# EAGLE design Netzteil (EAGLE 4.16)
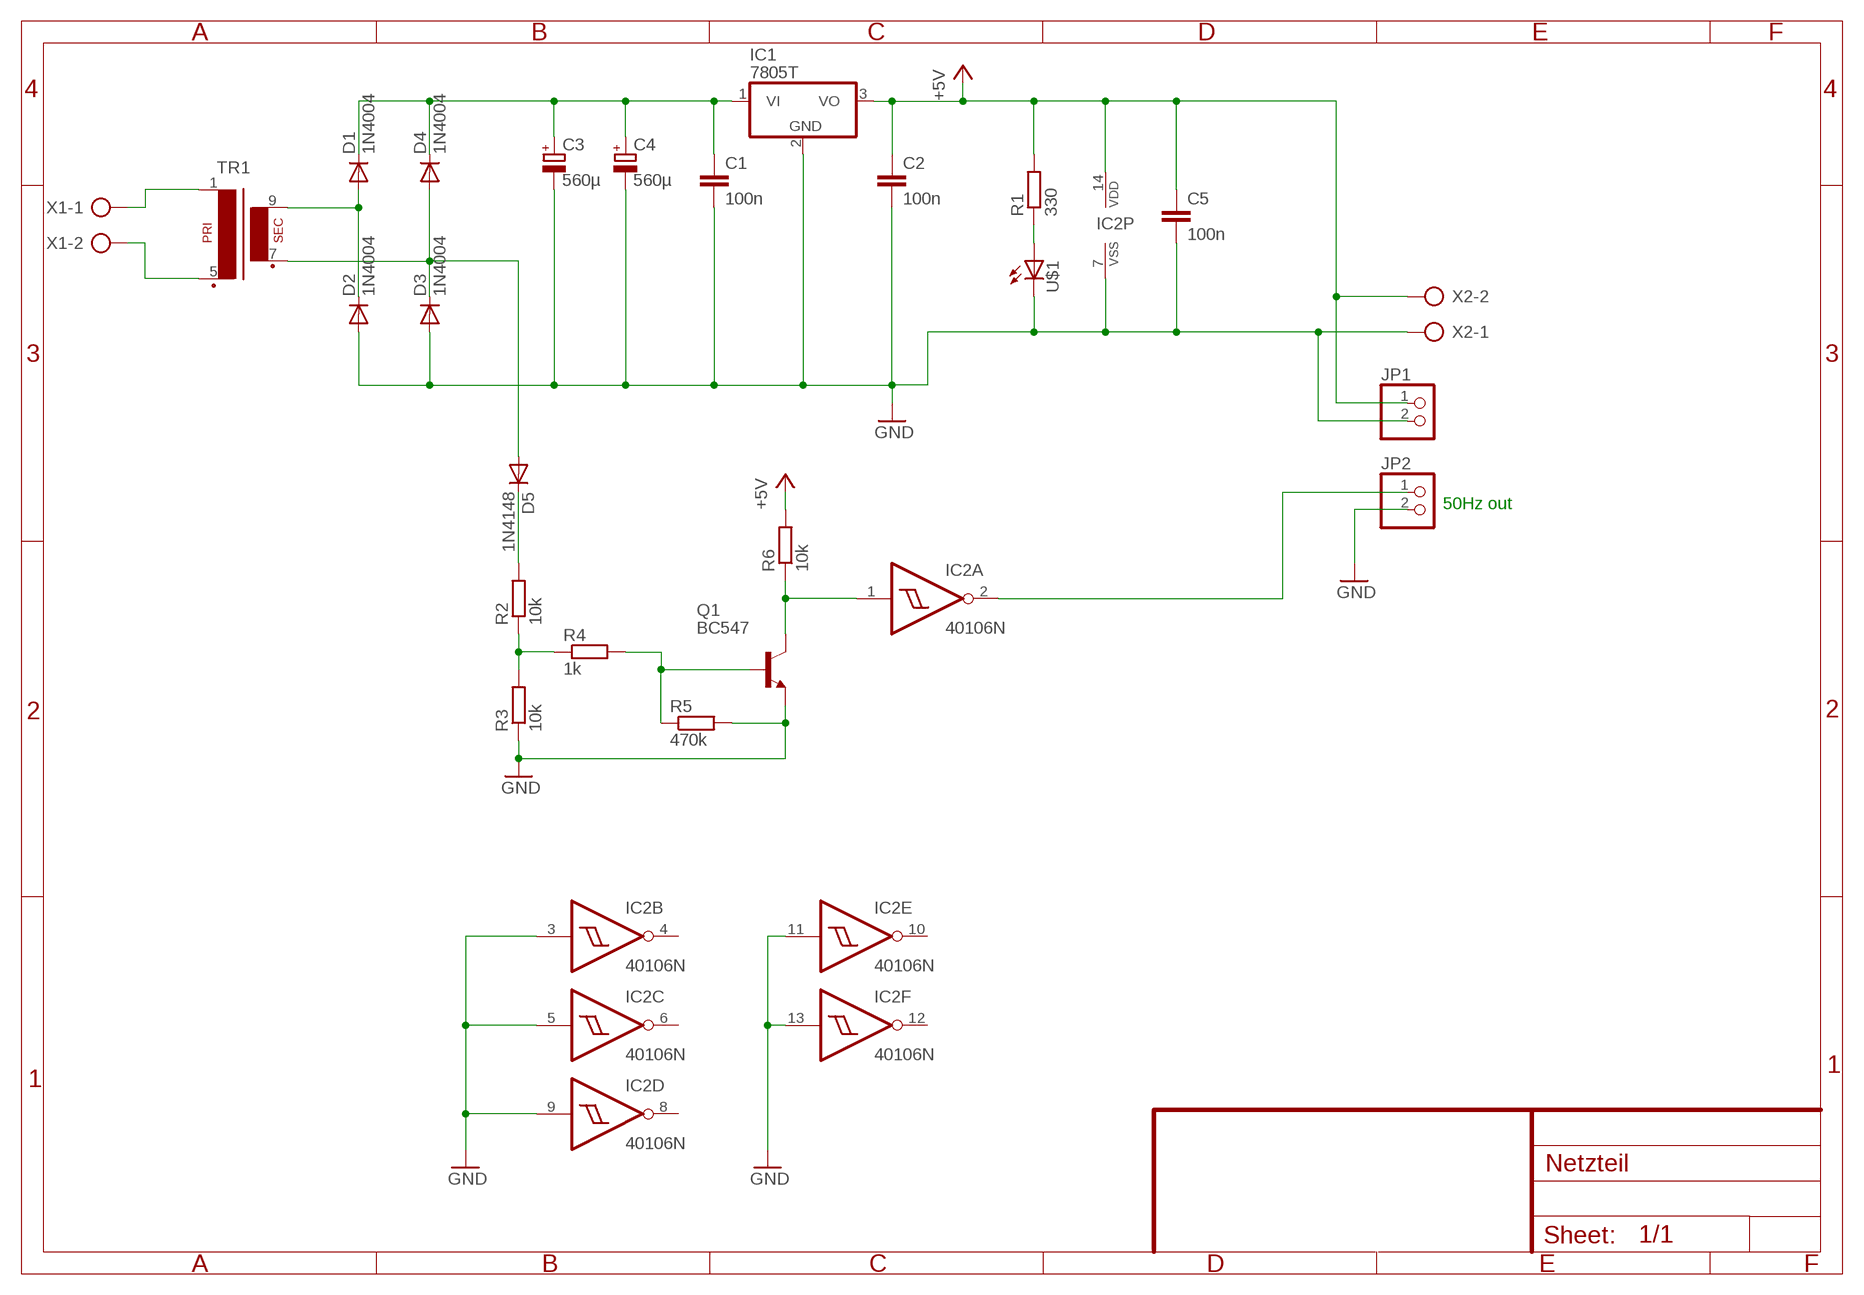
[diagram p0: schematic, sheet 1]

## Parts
C1  100n  C-EU050-024X044  [C050-024X044]
C2  100n  C-EU050-024X044  [C050-024X044]
C3  560µ  CPOL-EUE5-13  [E5-13]
C4  560µ  CPOL-EUE5-13  [E5-13]
C5  100n  C-EU050-024X044  [C050-024X044]
D1  1N4004  [DO41-10]
D2  1N4004  [DO41-10]
D3  1N4004  [DO41-10]
D4  1N4004  [DO41-10]
D5  1N4148  [DO35-10]
IC1  7805T  [TO220H]
IC2  40106N  [DIL14]
JP1  PINHD-1X2  [1X02]
JP2  PINHD-1X2  [1X02]
Q1  BC547  [TO92]
R1  330  R-EU_0207/10  [0207/10]
R2  10k  R-EU_0207/10  [0207/10]
R3  10k  R-EU_0207/10  [0207/10]
R4  1k  R-EU_0207/10  [0207/10]
R5  470k  R-EU_0207/10  [0207/10]
R6  10k  R-EU_0207/10  [0207/10]
TR1  EI30-1  [EI30-1]
U$1  LED5MM  [LED5MM]
X1  AK500/2  [AK500/2]
X2  AK500/2  [AK500/2]

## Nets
+5V: C2.1 C5.1 IC1.3(VO) IC2.14(P:VDD) JP1.1 R1.2 R6.2 X2.2
GND: C1.2 C2.2 C3.- C4.- C5.2 D2.A D3.A IC1.2(GND) IC2.3(B:I) IC2.5(C:I) IC2.7(P:VSS) IC2.9(D:I) IC2.11(E:I) IC2.13(F:I) JP1.2 JP2.2 Q1.1(E) R3.1 R5.2 U$1.K(C) X2.1
N$1: D1.A D2.C TR1.9
N$2: D3.C D4.A D5.A TR1.7
N$3: C1.1 C3.+ C4.+ D1.C D4.C IC1.1(VI)
N$5: TR1.1 X1.1
N$6: TR1.5 X1.2
N$9: R1.1 U$1.A
N$11: D5.C R2.2
N$12: R2.1 R3.2 R4.1
N$14: Q1.2(B) R4.2 R5.1
N$15: IC2.1(A:I) Q1.3(C) R6.1
N$17: IC2.2(A:O) JP2.1
Unconnected: IC2.4(B:O) IC2.6(C:O) IC2.8(D:O) IC2.10(E:O) IC2.12(F:O)

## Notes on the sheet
- 50Hz out

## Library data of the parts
C1 C2 C5 = rcl:C-EU: CAPACITOR, European symbol
C3 C4 = rcl:CPOL-EU: POLARIZED CAPACITOR, European symbol
D1-D4 = diode:1N4004: DIODE
D5 = diode:1N4148: DIODE
IC1 = linear:78*: Positive VOLTAGE REGULATOR Source: http://cache.national.com/ds/LM/LM78L05.pdf http://www.fairchildsemi.com/ds/LM/LM7805.pdf
IC2 = 40xx:40106: Hex SCHMITT TRIGGER
JP1 JP2 = pinhead:PINHD-1X2: PIN HEADER
Q1 = transistor-npn:BC547*: NPN Transistor
R1-R6 = rcl:R-EU_: RESISTOR, European symbol
TR1 = trafo:EI30-1: TRANSFORMER 1 primary winding, 1 secondary winding ERA
U$1 = led:LED: LED
X1 X2 = con-ptr500:AK500/2: CONNECTOR

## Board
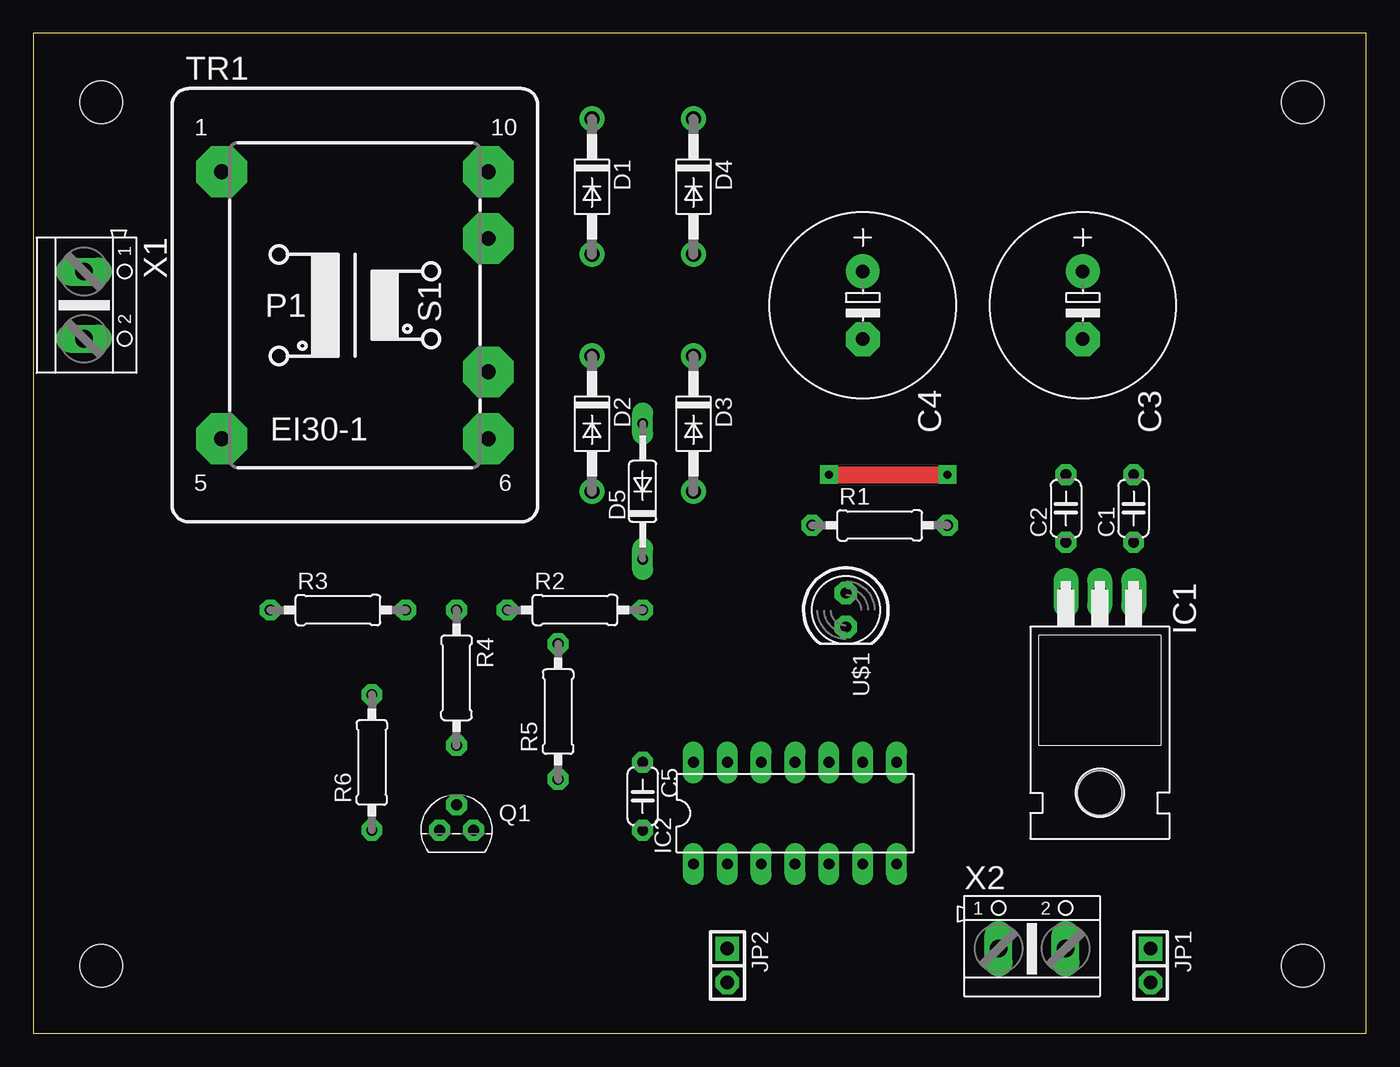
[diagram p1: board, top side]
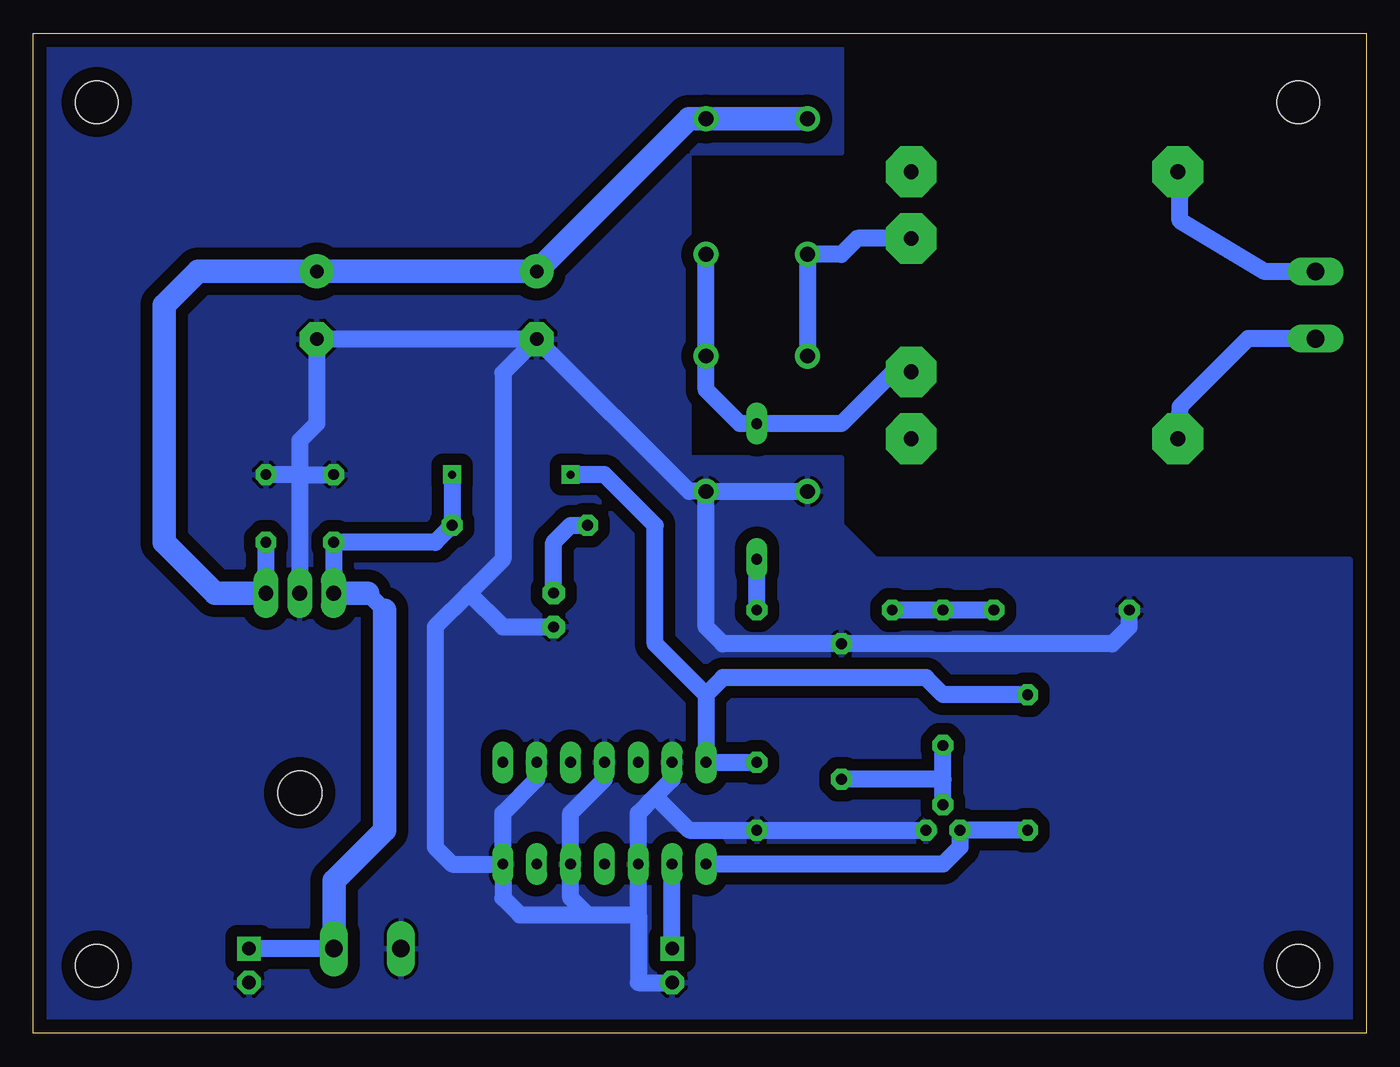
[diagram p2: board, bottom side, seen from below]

Size 100 x 75 mm. Coordinates in mm from the lower left corner, seen from the top.
Outline: 0,0 100,0 100,75 0,75 0,0
Copper layers (1*16): Top 0.035mm / dielectric 1.5mm / Bottom 0.035mm
Design rules "BWieck": minimum track width 12mil, minimum drill 24mil, track to track 35mil, track to pad 35mil, pad to pad 10mil, via to via 12mil, smd to smd 8mil, copper to edge 40mil, drill to drill 8mil, minimum pad ring 15mil, minimum via ring 15mil, stop-mask expansion 4mil, vias tented up to drill 0mil, thermal gap 10mil
Holes 3.2 mm at 5.08,69.85 5.08,5.08 95.25,5.08 95.25,69.85

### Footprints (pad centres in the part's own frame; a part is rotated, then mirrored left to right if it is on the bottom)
C050-024X044 = drill 0.813 octagon: 1 -2.54,0; 2 2.54,0
E5-13 = drill 1.016 pad 2.54 round: + -2.54,0 | drill 1.016 pad 2.54 octagon: - 2.54,0
DO41-10 = drill 1.118 round: A 5.08,0; C -5.08,0
DO35-10 = drill 0.813 long: A 5.08,0; C -5.08,0
TO220H = drill 1.118 long: 1 -2.54,-10.16; 2 0,-10.16; 3 2.54,-10.16 | hole 3.302: 0,4.826
DIL14 = drill 0.813 long: 1 -7.62,-3.81; 2 -5.08,-3.81; 3 -2.54,-3.81; 4 0,-3.81; 5 2.54,-3.81; 6 5.08,-3.81; 7 7.62,-3.81; 8 7.62,3.81; 9 5.08,3.81; 10 2.54,3.81; 11 0,3.81; 12 -2.54,3.81; 13 -5.08,3.81; 14 -7.62,3.81
1X02 = drill 1.016 square: 1 -1.27,0 | drill 1.016 octagon: 2 1.27,0
TO92 = drill 0.813 octagon: 1 1.27,0; 2 0,1.905; 3 -1.27,0
0207/10 = drill 0.813 octagon: 1 -5.08,0; 2 5.08,0
EI30-1 = drill 1.118 pad 3.81 octagon: 1 -10.008,10.008; 5 -10.008,-10.008; 6 10.008,-10.008; 7 10.008,-5.004; 9 10.008,5.004; 10 10.008,10.008
LED5MM = drill 0.813 pad 1.676 octagon: A -1.27,0; K 1.27,0
AK500/2 = drill 1.321 long: 1 -2.515,0; 2 2.515,0

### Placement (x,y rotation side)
C1  82.55,39.37 90 top
C2  77.47,39.37 90 top
C3  78.74,54.61 270 top
C4  62.23,54.61 270 top
C5  45.72,17.78 270 top
D1  41.91,63.5 270 top
D2  41.91,45.72 270 top
D3  49.53,45.72 270 top
D4  49.53,63.5 270 top
D5  45.72,40.64 90 top
IC1  80.01,22.86 180 top
IC2  57.15,16.51 0 top
JP1  83.82,5.08 270 top
JP2  52.07,5.08 270 top
Q1  31.75,15.24 0 top
R1  63.5,38.1 0 top
R2  40.64,31.75 0 top
R3  22.86,31.75 0 top
R4  31.75,26.67 270 top
R5  39.37,24.13 90 top
R6  25.4,20.32 90 top
TR1  24.13,54.61 0 top
U$1  60.96,31.75 270 top
X1  3.81,54.61 270 top
X2  74.93,6.35 0 top

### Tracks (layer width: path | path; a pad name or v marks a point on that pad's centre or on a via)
+5V  (via drill 0.6)
  Top 1.27: v59.69,41.91 v68.58,41.91
  Bottom 1.27: IC1.3 C2.1 69.85,36.83 R1.2 v68.58,41.91 | 74.93,33.02 73.66,31.75 | 49.53,25.4 IC2.14 C5.1 | 49.53,25.4 53.34,29.21 53.34,38.1 57.15,41.91 v59.69,41.91 | R6.2 31.75,25.4 33.02,26.67 48.26,26.67 49.53,25.4 | X2.2 JP1.1
  Bottom 1.778: IC1.3 74.93,33.02 | 73.66,31.75 73.66,15.24 77.44,11.46 X2.2
GND
  Bottom 1.27: D3.A D2.A | D3.A 50.8,40.64 C4.- | C4.- C3.- 78.74,45.72 80.01,44.45 80.01,41.91 | 80.01,41.91 C1.2 | 80.01,41.91 C2.2 | 80.01,41.91 IC1.2 | R3.1 17.78,30.48 19.05,29.21 R5.2 48.26,29.21 49.53,30.48 D3.A | 67.31,33.02 64.77,35.56 64.77,49.53 C4.- | 67.31,33.02 69.85,30.48 69.85,13.97 68.58,12.7 IC2.7 | U$1.K 64.77,30.48 67.31,33.02 | JP2.2 54.61,3.81 54.61,8.89 | 54.61,8.89 IC2.3 54.61,16.51 53.34,17.78 | 58.42,8.89 59.69,10.16 IC2.5 59.69,16.51 57.15,19.05 IC2.11 | 58.42,8.89 54.61,8.89 | IC2.7 64.77,10.16 63.5,8.89 58.42,8.89 | IC2.9 62.23,19.05 64.77,16.51 IC2.7 | IC2.13 52.07,19.05 53.34,17.78 | 53.34,17.78 50.8,15.24 C5.2 Q1.1
  pour Bottom: 39.37,74.93 98.42,74.93 99.69,73.66 99.69,0.64 99.06,0 1.27,0 0,1.27 0,34.29 1.27,35.56 36.83,35.56 39.37,38.1 39.37,43.18 50.8,43.18 50.8,66.04 39.37,66.04
N$1
  Bottom 1.27: TR1.9 38.18,59.61 39.37,58.42 D1.A D2.C
N$2
  Bottom 1.27: TR1.7 35.48,49.61 39.37,45.72 D5.A 46.99,45.72 49.53,48.26 D3.C D4.A
N$3
  Bottom 1.27: IC1.1 C1.1
  Bottom 1.778: D1.C D4.C 50.8,68.58 C4.+ C3.+ 87.63,57.15 90.17,54.61 90.17,36.83 86.36,33.02 IC1.1
N$5
  Bottom 1.27: X1.1 7.59,57.12 13.97,60.96 13.97,64.77 TR1.1
N$6
  Bottom 1.27: X1.2 8.87,52.09 13.97,46.99 TR1.5
N$9
  Bottom 1.27: R1.1 59.69,38.1 60.96,36.83 U$1.A
N$11
  Bottom 1.27: R2.2 D5.C
N$12
  Bottom 1.27: R2.1 R4.1 R3.2
N$14
  Bottom 1.27: Q1.2 31.75,19.05 | 31.75,19.05 R4.2 | 31.75,19.05 R5.1
N$15
  Bottom 1.27: R6.1 Q1.3 30.48,13.97 31.75,12.7 IC2.1
N$17
  Bottom 1.27: JP2.1 IC2.2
